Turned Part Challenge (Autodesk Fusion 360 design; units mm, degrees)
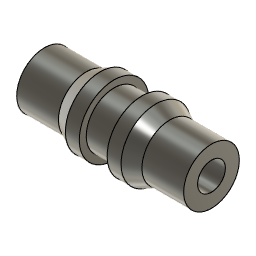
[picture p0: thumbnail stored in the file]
sketch "Sketch1" plane through (0, 0, 0) normal (0, 1, 0) x axis (1, 0, 0)
  line L1 (76.2, 0) -> (0, 0)
  line L2 (0, -12.7) -> (0, 0)
  line L3 (19.05, -12.7) -> (0, -12.7)
  line L4 (25.4, -15.875) -> (19.05, -12.7)
  line L5 (31.75, -15.875) -> (25.4, -15.875)
  line L6 (31.75, -12.7) -> (31.75, -15.875)
  line L7 (44.45, -12.7) -> (31.75, -12.7)
  line L8 (44.45, -15.875) -> (44.45, -12.7)
  line L9 (50.8, -15.875) -> (44.45, -15.875)
  line L10 (57.15, -12.7) -> (50.8, -15.875)
  line L11 (76.2, -12.7) -> (57.15, -12.7)
  line L12 (76.2, 0) -> (76.2, -12.7)
  point P1 (0, 0)
  point P2 (0, 0)
  point P4 (0, 0)
  point P3 (76.2, 0)
  point P9 (31.75, -12.7)
  point P10 (44.45, -12.7)
  point P7 (25.4, -15.875)
  point P8 (31.75, -15.875)
  point P5 (0, -12.7)
  point P6 (19.05, -12.7)
  coincident P1 P2
  horizontal L1
  coincident P1 P4
  perpendicular L1 L2
  perpendicular L2 L3
  perpendicular L2 L5
  perpendicular L5 L6
  perpendicular L6 L7
  perpendicular L5 L8
  perpendicular L8 L9
  parallel L1 L11
  perpendicular L1 L12
  collinear L3 L11
  collinear L5 L9
  collinear L3 L7
  equal L3 L11
  equal L5 L9
  equal L4 L10
  dimension "d1" distance P2 P3 = 76.2
  dimension "d2" distance P9 P10 = 12.7
  dimension "d3" distance P7 P8 = 6.35
  dimension "d4" distance P5 P6 = 19.05
  dimension "d5" distance P8 P9 = 3.175
  dimension "d6" = 25.4
revolve "Revolve1" sketch "Sketch1" AlongAngle 360
hole "Hole1" HoleDepth 50.8 HoleDiameter 12.7 TipAngle 118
